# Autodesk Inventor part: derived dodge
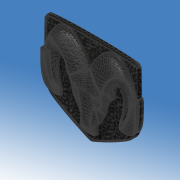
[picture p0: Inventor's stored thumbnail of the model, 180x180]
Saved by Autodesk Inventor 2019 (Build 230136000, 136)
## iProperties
Created: 2021-04
Part Number: derived dodge
Material: Generic
Document SubType Name: Modeling
Designer: Caden
Density: 1 g/cm^3
Appearance: Black Cast
Author: Caden
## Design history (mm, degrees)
derived "dodge_fixed4749.ipt" dims "d0" = 0.3125
sketch "Sketch1"
  geometry: L1 (0.711, -3.355)-(0.709, -3.273) reference; L2 (0.702, -2.949)-(0.709, -3.273) reference; L3 (0.693, -2.508)-(0.702, -2.949) reference; L4 (0.693, -2.508)-(0.687, -2.085) reference; L5 (0.687, -2.085)-(0.68, -1.632) reference; L6 (0.674, -1.196)-(0.68, -1.632) reference; L7 (0.673, -0.761)-(0.674, -1.196) reference; L8 (0.673, -0.761)-(0.672, -0.52) reference; L9 (0.674, -0.343)-(0.672, -0.52) reference; L10 (0.674, -0.343)-(0.687, 0.024) reference; L11 (0.702, 0.408)-(0.687, 0.024) reference; L12 (0.739, 0.69)-(0.702, 0.408) reference; L13 (0.773, 0.983)-(0.739, 0.69) reference; L14 (0.788, 1.015)-(0.773, 0.983) reference; L15 (0.841, 1.147)-(0.788, 1.015) reference; L16 (0.904, 1.309)-(0.841, 1.147) reference; L17 (0.907, 1.311)-(0.904, 1.309) reference; L18 (0.907, 1.311)-(0.991, 1.389) reference; L19 (0.991, 1.389)-(1.053, 1.448) reference; L20 (1.053, 1.448)-(1.07, 1.463) reference; L21 (1.07, 1.463)-(1.115, 1.475) reference; L22 (1.149, 1.484)-(1.115, 1.475) reference; L23 (1.235, 1.503)-(1.149, 1.484) reference; L24 (1.245, 1.501)-(1.235, 1.503) reference; L25 (1.282, 1.498)-(1.245, 1.501) reference; L26 (1.304, 1.498)-(1.282, 1.498) reference; L27 (1.373, 1.492)-(1.304, 1.498) reference; L28 (1.373, 1.492)-(1.375, 1.492) reference; L29 (1.375, 1.492)-(1.395, 1.492) reference; L30 (1.395, 1.492)-(1.403, 2.087) reference; L31 (1.452, 5.076)-(1.403, 2.087) reference; L32 (1.452, 5.076)-(1.504, 7.574) reference; L33 (1.504, 7.574)-(1.547, 9.209) reference; L34 (1.59, 10.171)-(1.547, 9.209) reference; L35 (1.59, 10.171)-(1.72, 10.512) reference; L36 (1.72, 10.512)-(1.78, 10.526) reference; L37 (1.837, 10.607)-(1.78, 10.526) reference; L38 (1.919, 10.678)-(1.837, 10.607) reference; L39 (1.944, 10.71)-(1.919, 10.678) reference; L40 (1.944, 10.71)-(1.941, 10.727) reference; L41 (1.917, 10.798)-(1.941, 10.727) reference; L42 (1.917, 10.798)-(2.085, 10.891) reference; L43 (2.055, 11.102)-(2.085, 10.891) reference; L44 (2.292, 11.169)-(2.055, 11.102) reference; L45 (2.292, 11.169)-(2.583, 11.211) reference; L46 (2.583, 11.211)-(2.922, 11.233) reference; L47 (2.922, 11.233)-(3.385, 11.261) reference; L48 (4.043, 11.322)-(3.385, 11.261) reference; L49 (4.043, 11.322)-(4.978, 11.398) reference; L50 (4.978, 11.398)-(6.273, 11.474) reference; L51 (6.273, 11.474)-(7.814, 11.545) reference; L52 (9.498, 11.605)-(7.814, 11.545) reference; L53 (9.498, 11.605)-(11.21, 11.649) reference; L54 (11.21, 11.649)-(12.842, 11.673) reference; L55 (12.842, 11.673)-(14.414, 11.68) reference; L56 (14.414, 11.68)-(15.95, 11.674) reference; L57 (15.95, 11.674)-(17.463, 11.664) reference; L58 (17.463, 11.664)-(18.976, 11.649) reference; L59 (20.509, 11.629)-(18.976, 11.649) reference; L60 (20.509, 11.629)-(22.081, 11.597) reference; L61 (23.714, 11.546)-(22.081, 11.597) reference; L62 (25.426, 11.473)-(23.714, 11.546) reference; L63 (27.106, 11.386)-(25.426, 11.473) reference; L64 (28.648, 11.289)-(27.106, 11.386) reference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; 1 further point
extrude "Extrusion1" cut sketch "Sketch1" distance "d1" = 25.4; taper "d2" = 0 deg
sketch "Sketch2"
  geometry: L1 (-4.853, 13.515)-(41.017, 13.515); L2 (41.017, 13.515)-(41.017, 21.816); L3 (41.017, 21.816)-(-4.853, 21.816); L4 (-4.853, 21.816)-(-4.853, 13.515); L5 (-1.164, -14.032)-(-4.853, -14.032); L6 (-4.853, -14.032)-(-4.853, 13.515); L7 (-4.853, 13.515)-(-1.164, 13.515); L8 (-1.164, 13.515)-(-1.164, -14.032); L9 (32.631, -12.257)-(39.599, -12.257); L10 (39.599, -12.257)-(39.599, 13.515); L11 (39.599, 13.515)-(32.631, 13.515); L12 (32.631, 13.515)-(32.631, -12.257); L13 (-4.853, -14.032)-(0.599, -14.032); L14 (0.599, -14.032)-(0.599, -9.981); L15 (0.599, -9.981)-(-4.853, -9.981); L16 (-4.853, -9.981)-(-4.853, -14.032); L17 (0.599, -9.981)-(5.454, -13.877); L18 (5.454, -13.877)-(14.437, -17.685); L19 (14.437, -17.685)-(15.832, -17.947); L20 (15.832, -17.947)-(18.303, -17.133); L21 (18.303, -17.133)-(29.723, -11.111); L22 (29.723, -11.111)-(32.631, -6.486); L23 (35.253, -12.257)-(17.642, -21.544); L24 (17.642, -21.544)-(11.588, -20.942); L25 (11.588, -20.942)-(3.743, -16.009); L26 (3.743, -16.009)-(0.599, -14.032); L27 (-1.164, -6.638)-(0.599, -9.981); 1 further point
  constraints: 54 end point, 9 parallel, 6 perpendicular, 4 horizontal, 4 point on line, 1 collinear
extrude "Extrusion2" cut sketch "Sketch2" stored distance "d3" = 25.4; taper "d4" = 0 deg
sketch "Sketch3"
  geometry: L1 (-0.977, -9.325)-(0.301, -9.987); L2 (0.301, -9.987)-(1.373, -11.424); L3 (1.373, -11.424)-(1.51, -14.528); L4 (1.51, -14.528)-(-1.479, -13.752); L5 (-1.479, -13.752)-(-4.014, -11.662); L6 (-4.014, -11.662)-(-3.419, -10.124); L7 (-3.419, -10.124)-(-2.359, -9.656); L8 (-2, -9.89)-(-1.424, -10.188); L9 (-1.424, -10.188)-(-0.977, -9.325); A1 r 0.392 centre (-2, -9.497) between (-2.359, -9.656) and (-2, -9.89); 1 further point
  constraints: 18 end point, 2 point on circle, 1 centre point, 1 parallel, 1 perpendicular, 1 point on line
extrude "Extrusion3" cut sketch "Sketch3" stored distance "d5" = 25.4; taper "d6" = 0 deg
feature "Solid1::dodge_fixed4749.ipt" dims "d0" = 0.3125
tag "TaggingFeature1"
node "Projected Loop1"
body "Solid1"
